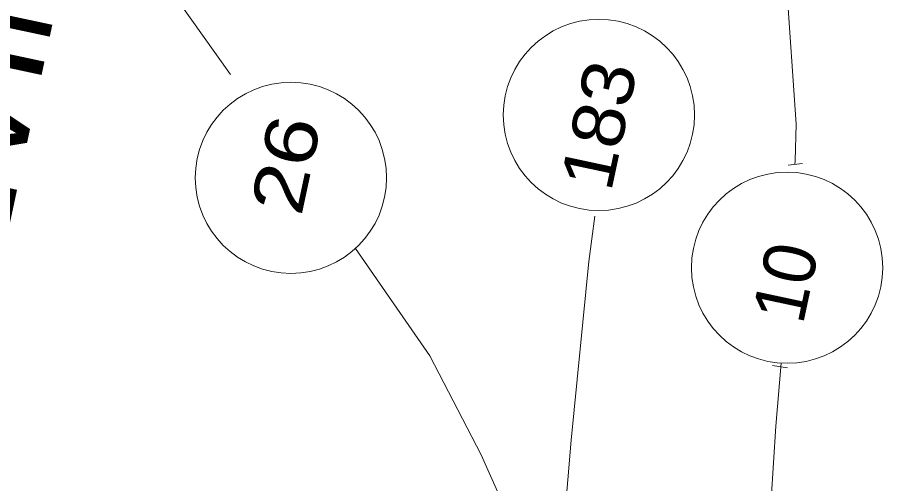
# Model space of a CAD drawing. Extents: x 2363411 to 2369126, y 6976878 to 6988319.
# Drawn here: x 2365871.2 to 2365955.9, y 6977193.1 to 6977238.8 of the extents above; entities that cross this region are included whole.
import ezdxf

# ---------------------------------------------------------------- set-up
doc = ezdxf.new("R2010")
doc.units = 0
doc.header["$LTSCALE"] = 2
doc.layers.add('62', color=7, linetype='Continuous', lineweight=13)
doc.layers.add('63', color=7, linetype='Continuous', lineweight=13)

msp = doc.modelspace()

# ---------------------------------------------------------------- linework, layer by layer
at = {"layer": '62'}
for p, q in [((2365885.393, 6977242.646), (2365892.097, 6977233.203)), ((2365947.455, 6977228.349), (2365947.351, 6977224.735)), ((2365946.665, 6977224.329), (2365948.079, 6977224.487)), ((2365947.325, 6977224.394), (2365947.351, 6977224.735)), ((2365927.159, 6977214.876), (2365927.764, 6977219.324)), ((2365911.612, 6977205.657), (2365904.332, 6977216.164)), ((2365945.46, 6977198.769), (2365945.993, 6977204.915)), ((2365945.163, 6977204.702), (2365946.611, 6977204.484))]:
    msp.add_line(p, q, dxfattribs=at)
for points in [[(2365947.455, 6977228.349), (2365946.525, 6977242.078), (2365942.171, 6977251.316), (2365936.413, 6977257.422)], [(2365923.878, 6977178.738), (2365925.447, 6977197.384), (2365927.159, 6977214.876)], [(2365911.612, 6977205.657), (2365916.624, 6977195.931), (2365924.198, 6977178.946)], [(2365945.46, 6977198.769), (2365944.099, 6977177.201), (2365935.888, 6977129.508), (2365935.556, 6977122.03)]]:
    msp.add_lwpolyline(points, dxfattribs=at)
for centre in [(2365928.149, 6977229.243), (2365898.001, 6977223.08), (2365946.571, 6977214.278)]:
    msp.add_circle(centre, 9.364, dxfattribs=at)
at = {"layer": '63'}
for p, q in [((2365885.393, 6977242.646), (2365892.097, 6977233.203)), ((2365947.455, 6977228.349), (2365947.351, 6977224.735)), ((2365946.665, 6977224.329), (2365948.079, 6977224.487)), ((2365947.325, 6977224.394), (2365947.351, 6977224.735)), ((2365927.159, 6977214.876), (2365927.764, 6977219.324)), ((2365911.612, 6977205.657), (2365904.332, 6977216.164)), ((2365945.46, 6977198.769), (2365945.993, 6977204.915)), ((2365945.163, 6977204.702), (2365946.611, 6977204.484))]:
    msp.add_line(p, q, dxfattribs=at)
for points in [[(2365947.455, 6977228.349), (2365946.525, 6977242.078), (2365942.171, 6977251.316), (2365936.413, 6977257.422)], [(2365923.878, 6977178.738), (2365925.447, 6977197.384), (2365927.159, 6977214.876)], [(2365911.612, 6977205.657), (2365916.624, 6977195.931), (2365924.198, 6977178.946)], [(2365945.46, 6977198.769), (2365944.099, 6977177.201), (2365935.888, 6977129.508), (2365935.556, 6977122.03)]]:
    msp.add_lwpolyline(points, dxfattribs=at)
for centre in [(2365928.149, 6977229.243), (2365898.001, 6977223.08), (2365946.571, 6977214.278)]:
    msp.add_circle(centre, 9.364, dxfattribs=at)

# ---------------------------------------------------------------- texts
at = {"layer": '62'}
for s, height, width, p in [('GRAPEVINE', 10.21, 1.05, (2365860.825, 6977173.432)), ('183', 5.099, 1.1, (2365929.33, 6977221.591)), ('26', 5.099, 1.25, (2365899.001, 6977219.212))]:
    msp.add_text(s, height=height, rotation=77.939, dxfattribs=dict(at, width=width)).set_placement(p)
msp.add_text('10', height=5.099, rotation=77.939, dxfattribs=at).set_placement((2365948.115, 6977208.603))
at = {"layer": '63'}
for s, height, width, p in [('GRAPEVINE', 10.21, 1.05, (2365860.825, 6977173.432)), ('183', 5.099, 1.1, (2365929.33, 6977221.591)), ('26', 5.099, 1.25, (2365899.001, 6977219.212))]:
    msp.add_text(s, height=height, rotation=77.939, dxfattribs=dict(at, width=width)).set_placement(p)
msp.add_text('10', height=5.099, rotation=77.939, dxfattribs=at).set_placement((2365948.115, 6977208.603))

doc.saveas('drawing.dxf')
